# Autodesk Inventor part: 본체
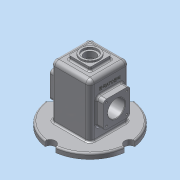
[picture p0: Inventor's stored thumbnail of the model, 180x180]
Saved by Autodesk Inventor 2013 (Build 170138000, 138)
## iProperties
Created: 2018-07
Part Number: 본체
Material: 알루미늄 6061
Document SubType Name: Modeling
Designer: Administrator
Density: 2.71 g/cm^3
Mass: 912.69 g
Surface Area: 1017.53 cm^2
Volume: 336.786 cm^3
Author: Administrator
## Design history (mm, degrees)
sketch "스케치1"
  geometry: L1 (-37, -37)-(37, -37); L2 (37, -37)-(37, 37); L3 (37, 37)-(-37, 37); L4 (-37, 37)-(-37, -37); L5 (-37, -37)-(37, 37); L6 (37, -37)-(-37, 37); 3 further points
  constraints: 12 end point, 3 midpoint, 2 parallel, 1 coincident, 1 horizontal, 1 perpendicular
  dimensions: "d0" = 74 distance of L3.end L2.end; "d1" = 74 distance of L2.end L1.end
extrude "돌출1" new body sketch "스케치1" distance "d2" = 110; taper "d3" = 0 deg
fillet "모깎기1" dims "d4" = 8
fillet "모깎기2" dims "d5" = 8
feature "쉘1" dims "d6" = 5
sketch "스케치2"
  geometry: L1 (-20, -20)-(20, -20); L2 (20, -20)-(20, 20); L3 (20, 20)-(-20, 20); L4 (-20, 20)-(-20, -20); L5 (-20, -20)-(20, 20); L6 (20, -20)-(-20, 20); 1 further point
  constraints: 12 end point, 2 midpoint, 2 parallel, 2 perpendicular, 1 horizontal
  dimensions: "d7" = 40 distance of L2.end L3.end
extrude "돌출2" join sketch "스케치2" distance "d9" = 7; taper "d10" = 0 deg
sketch "스케치3"
  geometry: C1 r 17.5 at (0, 0); 1 further point
  constraints: 1 centre point, 1 coincident
  dimensions: "d11" = 35 diameter of C1
extrude "돌출3" join sketch "스케치3" distance "d13" = 3; taper "d14" = 0 deg
hole "구멍1" diameter "d17" = 21; stored, may be unused: countersink angle "d21" = 90 deg, drill point angle "d23" = 118 deg; dims "d15" = 10, "d16" = 10, "d18" = 6, "d19" = 28, "d20" = 4, "d22" = 8
sketch "스케치4"
  geometry: L1 (-37, 29)-(-37, -29) reference; L2 (-29, -37)-(29, -37) reference; L3 (37, -29)-(37, 29) reference; L4 (29, 37)-(-29, 37) reference; A1 r 75 centre (0, 0) between (-74.333, -9.978) and (-9.978, -74.333); A2 r 10 centre (0, -75) between (9.978, -74.333) and (-9.978, -74.333); A3 r 10 centre (75, 0) between (74.333, -9.978) and (74.333, 9.978); A4 r 10 centre (0, 75) between (-9.978, 74.333) and (9.978, 74.333); A5 r 10 centre (-75, 0) between (-74.333, -9.978) and (-74.333, 9.978); A6 r 75 centre (0, 0) between (-74.333, 9.978) and (-74.333, -9.978); A7 r 10 centre (-75, 0) between (-74.333, 9.978) and (-74.333, -9.978); A8 r 75 centre (0, 0) between (-9.978, 74.333) and (-74.333, 9.978); A9 r 75 centre (0, 0) between (9.978, 74.333) and (-9.978, 74.333); A10 r 75 centre (0, 0) between (74.333, -9.978) and (74.333, 9.978); A11 r 75 centre (0, 0) between (74.333, 9.978) and (9.978, 74.333); A12 r 75 centre (0, 0) between (9.978, -74.333) and (74.333, -9.978); A13 r 75 centre (0, 0) between (-9.978, -74.333) and (9.978, -74.333); A14 r 10 centre (0, -75) between (-9.978, -74.333) and (9.978, -74.333); A15 r 10 centre (0, 75) between (9.978, 74.333) and (-9.978, 74.333); A16 r 10 centre (75, 0) between (74.333, 9.978) and (74.333, -9.978); A17 r 8 centre (-29, -29) between (-37, -29) and (-29, -37) reference; A18 r 8 centre (29, -29) between (29, -37) and (37, -29) reference; A19 r 8 centre (29, 29) between (37, 29) and (29, 37) reference; A20 r 8 centre (-29, 29) between (-29, 37) and (-37, 29) reference; 1 further point
  constraints: 47 point on circle, 16 centre point, 2 horizontal alignment, 2 vertical alignment, 1 coincident
  dimensions: "d24" = 150 diameter of A1; "d26" = 10 radius of A2; "d27" = 10 radius of A3; "d28" = 10 radius of A4; "d29" = 10 radius of A5
extrude "돌출4" join sketch "스케치4" distance "d30" = 10; taper "d31" = 0 deg
sketch "스케치5"
  geometry: L1 (54, -72)-(4, -72); L2 (4, -72)-(4, -22); L3 (4, -22)-(54, -22); L4 (54, -22)-(54, -72); L5 (54, -72)-(4, -22); L6 (4, -72)-(54, -22); L7 (19.022, -102)-(38.978, -102) reference; L8 (103.333, -102)-(38.978, -102) reference; 4 further points
  constraints: 12 end point, 4 midpoint, 2 parallel, 2 perpendicular, 1 horizontal, 1 vertical alignment
  dimensions: "d32" = 50 distance of L2.end L3.end; "d34" = 55 distance from line of L8 point (29, -47)
extrude "돌출5" join sketch "스케치5" distance "d35" = 13; taper "d36" = 0 deg
sketch "스케치6"
  geometry: L1 (58, 0)-(0, 0) reference; L2 (103.333, 0)-(38.978, 0) reference; C1 r 25 at (29, 55); 2 further points
  constraints: 1 centre point, 1 midpoint, 1 vertical alignment
  dimensions: "d37" = 55 distance from line of L2 C1.centre; "d38" = 50 diameter of C1
extrude "돌출6" join sketch "스케치6" distance "d39" = 7; taper "d40" = -20 deg
sketch "스케치7"
  geometry: L1 (103.333, -102)-(38.978, -102) reference; L2 (0, -102)-(58, -102) reference; 3 further points
  constraints: 1 midpoint, 1 vertical alignment
  dimensions: "d41" = 55 distance from line of L1 point (29, -47)
hole "구멍2" sketch "스케치7" at (29, -47) diameter "d42" = 32; stored, may be unused: countersink angle "d46" = 90 deg, drill point angle "d48" = 118 deg; dims "d43" = 6, "d44" = 28, "d45" = 4, "d47" = 8
fillet "모깎기3" dims "d49" = 6
sketch "스케치8"
  geometry: A1 r 6 centre (48, -28) between (54, -28) and (48, -22) reference; A2 r 6 centre (10, -28) between (10, -22) and (4, -28) reference; A3 r 6 centre (10, -66) between (4, -66) and (10, -72) reference; A4 r 6 centre (48, -66) between (48, -72) and (54, -66) reference; 5 further points
  constraints: 4 coincident
hole "구멍3" sketch "스케치8" at (10, -28), (10, -66), (48, -66), (48, -28) diameter "d50" = 3.242; stored, may be unused: countersink angle "d54" = 90 deg, drill point angle "d56" = 118 deg; dims "d51" = 8, "d52" = 28, "d53" = 4, "d55" = 10
sketch "스케치9"
  geometry: A1 r 6 centre (6, 38) between (6, 44) and (0, 38) reference; A2 r 6 centre (6, 0) between (0, 0) and (6, -6) reference; A3 r 6 centre (44, 0) between (44, -6) and (50, 0) reference; A4 r 6 centre (44, 38) between (50, 38) and (44, 44) reference; 5 further points
  constraints: 4 coincident
hole "구멍4" sketch "스케치9" at (6, 38), (6, 0), (44, 0), (44, 38) diameter "d57" = 3.242; stored, may be unused: countersink angle "d61" = 90 deg, drill point angle "d63" = 118 deg; dims "d58" = 8, "d59" = 28, "d60" = 4, "d62" = 10
sketch "스케치10"
  geometry: L1 (46.5, 18)-(11.5, 18) reference; L2 (66, -92)-(66, 0) reference; 2 further points
  constraints: 1 other
  dimensions: "d64" = 30 distance from line of L1 point (29, -12); "d65" = 37 distance from line of L2 point (29, -12)
feature "엠보싱1" sketch "스케치10" dims "d0" = 74, "d1" = 74, "d66" = 0.5, "d67" = 0
fillet "모깎기4" dims "d68" = 3
fillet "모깎기5" dims "d69" = 3
chamfer "모따기1" distance "d70" = 1; stored, may be unused: second distance "d71" = 2, angle "d72" = 45 deg
node "솔리드1"
mirror "대칭1"
